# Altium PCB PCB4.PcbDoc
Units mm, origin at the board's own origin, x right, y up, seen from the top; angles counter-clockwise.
Board outline 26 x 20 mm, 2 copper layers (Top Layer, Bottom Layer); 13 components, 19 nets, 46 pads, 6 vias.
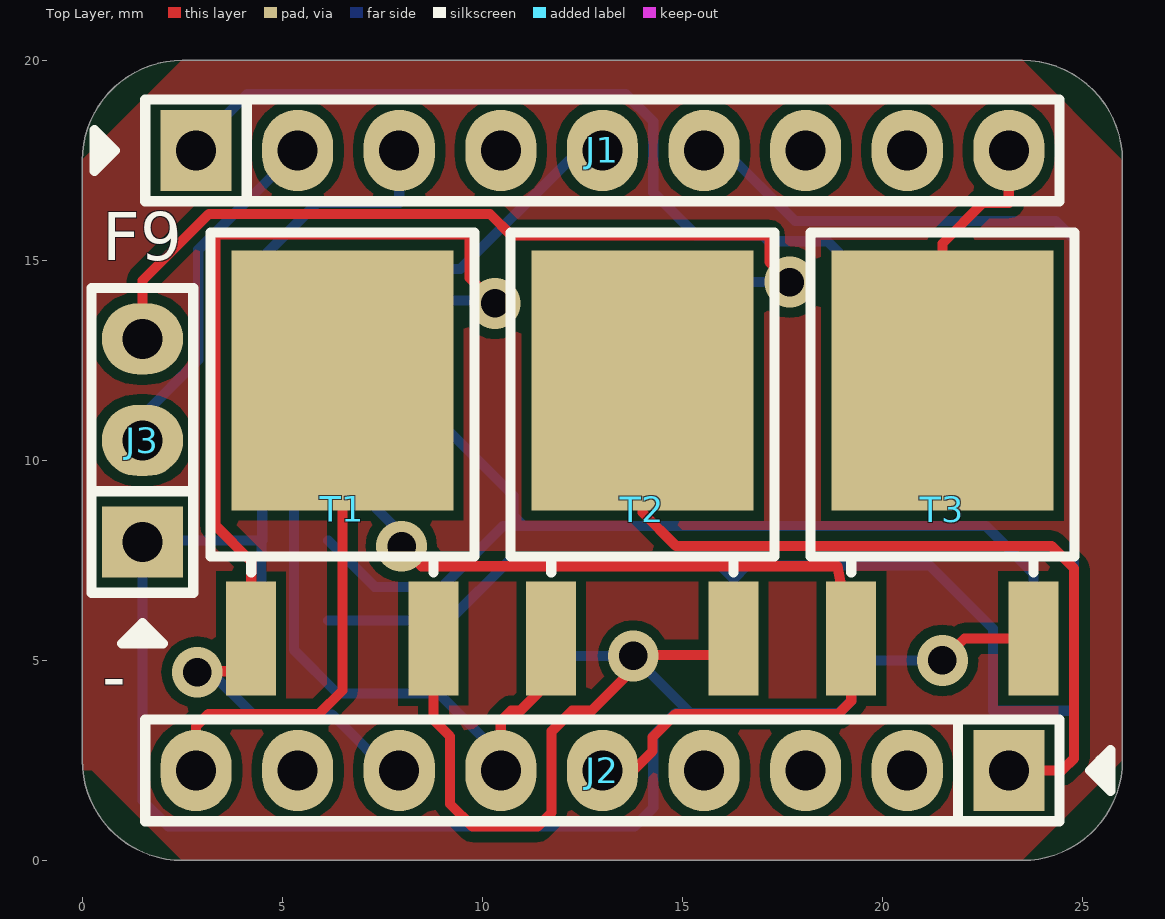
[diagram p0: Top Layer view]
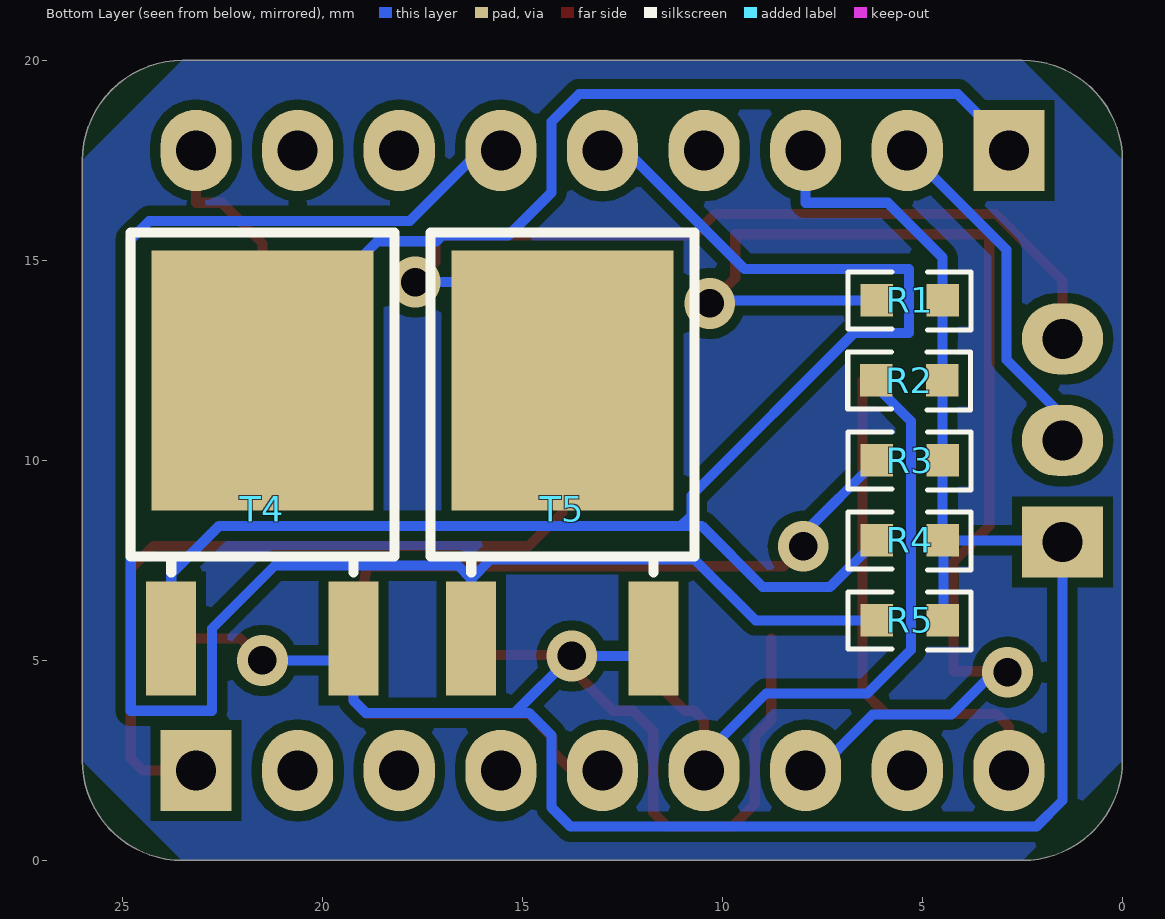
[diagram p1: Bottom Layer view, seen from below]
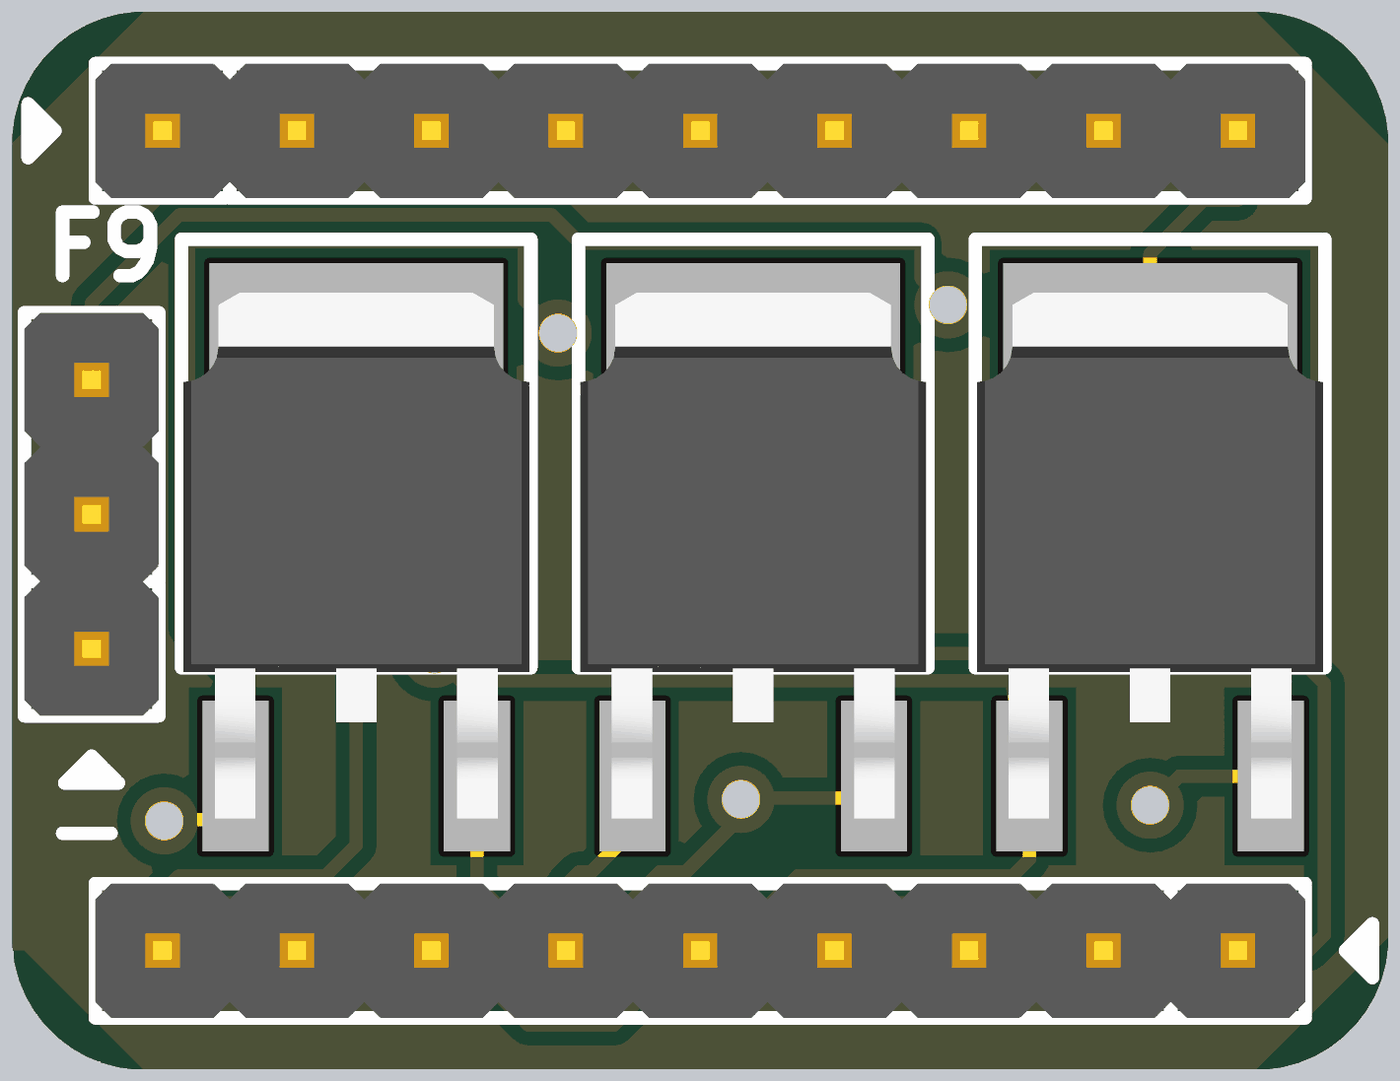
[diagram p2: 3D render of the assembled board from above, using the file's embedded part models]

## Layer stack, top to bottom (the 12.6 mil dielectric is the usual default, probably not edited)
Top Solder: solder mask 0.0102, Solder Resist, Dk 3.5
Top Layer: signal copper 0.0356
Dielectric 1: dielectric 0.32, FR-4, Dk 4.8
Bottom Layer: signal copper 0.0356
Bottom Solder: solder mask 0.0102, Solder Resist, Dk 3.5

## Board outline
2.5,0 cw(c2.5,2.5) 0,2.5 0,17.5 cw(c2.5,17.5) 2.5,20 23.492,20 cw(c23.492,17.492) 26,17.492 26,2.5 cw(c23.5,2.5) 23.5,0

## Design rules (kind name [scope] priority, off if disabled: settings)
Clearance [All] p1: gap=0.254
PolygonConnect [All] p1: connectstyle=Relief reliefconductorwidth=0.254 reliefentries=4 polygonreliefangle="90 Angle" airgapwidth=0.254
RoutingVias [All] p1: holewidth=0.711 width=1.27 viastyle="Through Hole" minholewidth=0.711 minwidth=1.27 maxholewidth=0.711 maxwidth=1.27
SolderMaskExpansion [All] p1: expansion=0.102
Width [All] p1: maxlimit=0.254 minlimit=0.254 preferedwidth=0.254
29 further rules are at their usual default settings.

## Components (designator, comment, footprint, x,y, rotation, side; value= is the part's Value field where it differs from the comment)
J1 "HDR1x9" PIN-9-2.54-1.0 13,17.75 r0 top
J2 "HDR1x9" PIN-9-2.54-1.0 13,2.25 r180 top
J3 "HDR1x3" PIN-3-2.54-1.0 1.5,10.5 r90 top
R1 "Res2" 0603 4.5,14 r0 bottom
R2 "Res2" 0603 4.504,12 r0 bottom
R3 "Res2" 0603 4.5,10 r0 bottom
R4 "Res2" 0603 4.5,8 r0 bottom
R5 "Res2" 0603 4.5,6 r0 bottom
T1 "BT136S-600E" TO-252 6.5,12 r0 top
T2 "BT136S-600E" TO-252 14,12 r0 top
T3 "BT136S-600E" TO-252 21.5,12 r0 top
T4 "BT136S-600E" TO-252 21.5,12 r180 bottom
T5 "BT136S-600E" TO-252 14,12 r180 bottom

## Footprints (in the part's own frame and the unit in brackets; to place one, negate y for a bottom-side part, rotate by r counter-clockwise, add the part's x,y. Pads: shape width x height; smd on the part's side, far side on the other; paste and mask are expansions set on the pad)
0603 [mil]
  rect 32x32 smd: 1(-0.17,-0.01) 2(64.83,-0.01)
  silkscreen extent -28,-28 93,29
PIN-3-2.54-1.0 [mil] "Pin Header"
  rect 70x80 hole 39.37: 1(-100,0)
  oval 70x80 hole 39.37: 2(0,0) 3(100,0)
  silkscreen extent -200,-50 150,50, body extent -150,-50 150,50, height 398
PIN-9-2.54-1.0 [mil] "Pin Header"
  rect 70x80 hole 39.37: 1(-400,0)
  oval 70x80 hole 39.37: 2(-300,0) 3(-200,0) 4(-100,0) 5(0,0) 6(100,0) 7(200,0) 8(300,0) 9(400,0)
  silkscreen extent -500,-50 450,50, body extent -450,-50 450,50, height 398
TO-252 [mm] "TO-252, DPAK"
  rect 1.25x2.85 smd: 1(-2.28,-6.45) 3(2.28,-6.45)
  rect 5.55x6.5 smd: 4(0,0)
  silkscreen extent -3.3,-4.8 3.3,3.7, body extent -3.27,-7.25 3.27,2.69, height 2.41

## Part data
J1 J2 J3: "Connector"
R1 R2 R3 R4 R5: "Resistor"
T1 T2 T3 T4 T5: "Triac"

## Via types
v1: diameter 1.27, hole 0.711, Top Layer to Bottom Layer, tented both sides, 6 vias

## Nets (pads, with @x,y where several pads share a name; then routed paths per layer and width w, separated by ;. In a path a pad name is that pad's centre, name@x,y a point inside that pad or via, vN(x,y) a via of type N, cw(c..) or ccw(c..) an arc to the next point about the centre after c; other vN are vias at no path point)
3.3V: J1.4
5V: J1.2 J3.2 | length 8.9
  Bottom Layer w0.254: J3.2 1.5,11.117 2.897,12.514 2.897,15.267 J1.2
A1: J2.9 T1.4 | length 12.9
  Top Layer w0.254: J2.9 2.84,3.352 3.152,3.664 5.916,3.664 6.5,4.248 T1.4
A2: J2.1 T2.4 | length 21.2
  Top Layer w0.254: T2.4 14,8.7 14.836,7.864 24.225,7.864 24.793,7.296 24.793,2.555 24.488,2.25 J2.1
A3: J1.9 T3.4 | length 6.8
  Top Layer w0.254: T3.4 21.5,15.424 22.516,16.44 23.16,16.44 J1.9
A4: J1.1 T4.4 | length 23.7
  Bottom Layer w0.254: J1.1 2.84,17.881 4.117,19.158 13.584,19.158 14.27,18.472 14.27,16.705 15.344,15.631 17.002,15.631 17.156,15.477 18.625,15.477 21.5,12.603 T4.4
A5: J3.3 T5.4 | length 25.6
  Top Layer w0.254: J3.3 1.5,14.5 3.161,16.161 10.188,16.161 10.717,15.631 17.173,15.631 17.173,14.967 v1(17.681,14.459)
  Bottom Layer w0.254: T5.4 14,14.459 v1(17.681,14.459)
CON0: J2.8
CON1: J2.7 R1.2 T1.1 | length 31.6
  Top Layer w0.254: v1(2.873,4.705) 2.898,4.731 4.22,4.731 T1.1 4.22,7.473 3.33,8.363 3.33,15.611 3.371,15.653 9.68,15.653 9.68,14.56 v1(10.315,13.925)
  Bottom Layer w0.254: v1(2.873,4.705) 3.211,4.705 4.27,3.647 6.242,3.647 7.92,1.969 J2.7 ; R1.2 10.24,14 v1(10.315,13.925)
CON2: J2.6 R2.2 T2.1 | length 17.6
  Top Layer w0.254: J2.6 10.46,3.486 10.714,3.74 10.943,3.74 11.72,4.517 T2.1
  Bottom Layer w0.254: R2.2@6.229,11.922 5.286,10.979 5.286,5.264 6.378,4.172 8.911,4.172 10.46,2.622 J2.6
CON3: J2.5 R3.2 T3.1 | length 24.6
  Top Layer w0.254: v1(7.978,7.855) 8.477,7.356 18.881,7.356 T3.1 19.22,3.984 18.9,3.664 14.836,3.664 14.252,3.08 14.252,2.733 13.769,2.25 J2.5
  Bottom Layer w0.254: R3.2 7.978,8.169 v1(7.978,7.855)
CON4: J1.5 R4.2 T4.1 | length 39.5
  Bottom Layer w0.254: R4.2 7.308,6.839 8.996,6.839 10.52,8.363 11.026,8.363 ; J1.5 13,17.481 12.144,17.481 9.451,14.789 5.336,14.789 5.336,13.189 6.708,13.189 10.772,9.125 10.772,8.617 11.026,8.363 ; T4.1 23.78,7.166 22.583,8.363 11.026,8.363
CON5: J1.6 R5.2 T5.1 | length 45.8
  Bottom Layer w0.254: R5.2 9.173,6 10.698,7.525 15.797,7.525 16.28,7.042 ; J1.6 16.053,17.75 17.818,15.985 24.333,15.985 24.793,15.526 24.793,3.74 22.761,3.74 22.761,5.797 21.186,7.372 16.61,7.372 16.28,7.042 ; T5.1 16.28,7.042
GND: J1.3 J3.1 R1.1 R2.1 R3.1 R4.1 R5.1 T1.3 T2.3 T3.3 T4.3 T5.3 | length 69.2
  Top Layer w0.254: T1.3 8.78,3.511 9.19,3.101 9.19,1.41 9.756,0.844 11.374,0.844 11.73,1.2 11.73,3.232 12.238,3.74 12.728,3.74 14.125,5.137 16.28,5.137 T2.3 ; v1(21.5,5) 22.05,5.55 T3.3
  Bottom Layer w0.254: J3.1@1.5,7.678 1.5,1.5 2.156,0.844 13.795,0.844 14.27,1.32 14.27,3.123 14.836,3.689 15.192,3.689 ; J3.1@1.5,8 R4.1 R3.1 ; R4.1@4.473,8 4.473,6.023 R5.1 ; R3.1@4.5,10.004 R2.1 4.5,12.986 4.496,12.99 R1.1 4.496,15.068 5.867,16.44 7.92,16.44 J1.3 ; T5.3 11.72,5.112 v1(13.769,5.112) 15.192,3.689 ; T4.3 19.22,3.994 18.915,3.689 15.192,3.689 ; T4.3@19.77,5 v1(21.5,5)
RX: J1.8
SCK: J1.7
SCL: J2.3
SDA: J2.4
TX: J2.2

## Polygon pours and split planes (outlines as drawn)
no net on Bottom Layer "Top Layer-No Net" (solid, pour order 10): -0.012,17.5 2.488,20 2.5,20 23.48,20 23.492,20.012 26,17.504 26,17.492 26,2.512 26.012,2.5 23.512,0 23.5,0 2.512,0 2.5,-0.012 0,2.488 0,2.5 0,17.488 -0.012,17.5
no net on Top Layer "Top Layer-No Net" (solid, pour order 12): -0.012,17.5 2.488,20 2.5,20 23.48,20 23.492,20.012 26,17.504 26,17.492 26,2.5 23.5,0 2.512,0 2.5,-0.012 0.233,2.255 0.012,2.255 0.012,17.476 -0.012,17.5

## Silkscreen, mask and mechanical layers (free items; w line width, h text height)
Top Overlay:
  text "F9" at 0.5,15 h1.2
  text "-" at 0.5,4 h1.2
Mechanical 1:
  the board outline again, w0.254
